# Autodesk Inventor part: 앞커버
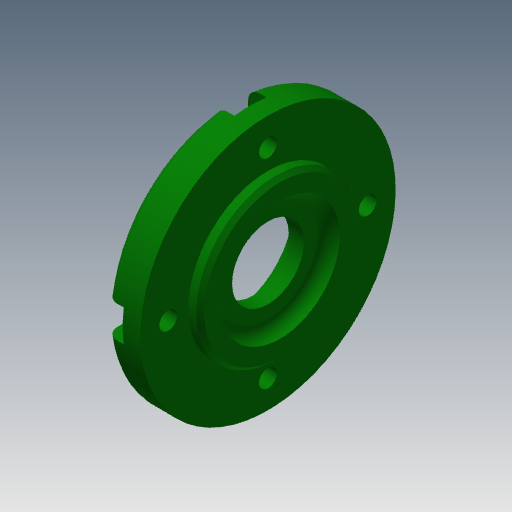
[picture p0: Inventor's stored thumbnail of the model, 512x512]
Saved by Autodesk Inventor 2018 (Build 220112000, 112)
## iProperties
Created: 2019-01
Part Number: 앞커버
Material: 알루미늄 6061
Document SubType Name: Modeling
Designer: mduedu
Density: 2.71 g/cm^3
Appearance: 진녹색
Mass: 65.0162 g
Surface Area: 90.7546 cm^2
Volume: 23.9912 cm^3
Author: mduedu
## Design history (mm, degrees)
sketch "스케치1"
  geometry: L1 (0, 0)-(9, 0); L2 (9, 0)-(9, 32); L3 (9, 32)-(0, 32); L4 (0, 32)-(0, 0); L5 (9, 0)-(12, 0); L6 (12, 0)-(12, 20); L7 (12, 20)-(9, 20); L8 (9, 20)-(9, 0)
  constraints: 16 end point, 4 parallel, 2 horizontal, 2 perpendicular
  dimensions: "d0" = 12 distance between parallel lines of L6 L4; "d2" = 64 diameter of L3 L1; "d3" = 40 diameter of L7 L5; "d4" = 3 distance between parallel lines of L6 L2
revolve "회전1" sketch "스케치1" stored, may be unused: angle "d5" = 90 deg
sketch "스케치2"
  geometry: L1 (0, -32)-(0, 32) reference; L2 (0, 32)-(9, 32) reference; L3 (9, 32)-(9, 20) reference; L4 (9, 20)-(12, 20) reference; L5 (12, 20)-(12, -20) reference; L6 (12, -20)-(9, -20) reference; L7 (9, -20)-(9, -32) reference; L8 (9, -32)-(0, -32) reference; L9 (0, 0)-(5.2, 0); L10 (5.2, 0)-(5.2, 15); L11 (5.2, 15)-(0, 15); L12 (0, 15)-(0, 0); L13 (5.2, 0)-(9, 0); L14 (9, 0)-(9, 9); L15 (9, 9)-(5.2, 9); L16 (5.2, 9)-(5.2, 0); L17 (9, 0)-(12, 0); L18 (12, 0)-(12, 15); L19 (12, 15)-(9, 15); L20 (9, 15)-(9, 0)
  constraints: 24 end point, 6 parallel, 3 horizontal, 3 perpendicular, 1 point on line
  dimensions: "d6" = 3 distance of L18.end L19.end; "d8" = 5.2 distance of L10.end L11.end; "d9" = 30 diameter of L11 L9; "d10" = 18 diameter of L15 L13; "d11" = 30 diameter of L19 L17
revolve "회전2" sketch "스케치2" stored, may be unused: angle "d12" = 90 deg
chamfer "모따기1" distance "d13" = 0.5; stored, may be unused: second distance "d14" = 2, angle "d15" = 30 deg
fillet "모깎기1" dims "d16" = 0.5
fillet "모깎기2" dims "d17" = 3
fillet "모깎기3" dims "d18" = 3
chamfer "모따기2" distance "d24" = 1; stored, may be unused: second distance "d25" = 2, angle "d26" = 45 deg
sketch "스케치3" dims "d19" = 50
  geometry: 6 further points
  constraints: 2 vertical alignment, 1 coincident, 7 other
  dimensions: "d22" = 360 deg dimension on point (0, 0) point (0, 25) (derived)
sketch "스케치4"
  geometry: 4 further points
  constraints: 4 other
hole "구멍1" sketch "스케치4" at (-25, 0), (0, -25), (25, 0), (0, 25) diameter "d27" = 4.5; stored, may be unused: countersink angle "d31" = 90 deg, drill point angle "d33" = 0 deg; dims "d28" = 6, "d29" = 8, "d30" = 4.6, "d32" = 8
sketch "스케치5"
  geometry: L1 (-4, 0)-(-4, 6.749); L2 (4, 0)-(4, 6.749); A1 r 4 centre (0, 0) between (0, 4) and (-4, 0) reference; A2 r 32 centre (0, -25) between (-4, 6.749) and (4, 6.749) reference; A3 r 4 centre (0, 0) between (-4, 0) and (4, 0); A4 r 32 centre (0, -25) between (4, 6.749) and (-4, 6.749); A5 r 4 centre (0, 0) between (4, 0) and (-4, 0); 1 further point
  constraints: 10 point on circle, 4 end point, 3 centre point, 2 coincident, 2 tangent, 1 parallel, 1 vertical
extrude "돌출1" cut sketch "스케치5" extent not by distance; stored distance "d34" = 10; taper "d35" = 0 deg
node "솔리드1"
pattern_circular "원형 패턴1" dims angle "d37" = 360 deg
node "절단 모서리 투영1"
